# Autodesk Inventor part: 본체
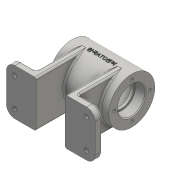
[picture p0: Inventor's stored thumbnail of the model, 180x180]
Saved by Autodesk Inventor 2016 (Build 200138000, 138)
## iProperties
Created: 2017-02
Part Number: 본체
Material: 일반
Document SubType Name: Modeling
Designer: CAMTIC
Density: 1 g/cm^3
Appearance: 기본값
Author: CAMTIC
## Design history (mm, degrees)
sketch "스케치1"
  geometry: L1 (52, 27)-(-52, 27); L2 (-52, 27)-(-52, -27); L3 (-52, -27)-(52, -27); L4 (52, -27)-(52, 27); L5 (52, 27)-(-52, -27); L6 (-52, 27)-(52, -27); 1 further point
  constraints: 12 end point, 2 midpoint, 2 parallel, 1 horizontal, 1 perpendicular
  dimensions: "d0" = 104 distance of L2.end L3.end; "d1" = 54 distance of L1.end L2.end
extrude "돌출1" new body sketch "스케치1" distance "d2" = 8; taper "d3" = 0 deg
sketch "스케치2"
  geometry: L1 (52, 0)-(52, 23.504) reference; L2 (35, -3.752)-(69, -3.752); L3 (69, -3.752)-(69, 27.256); L4 (69, 27.256)-(35, 27.256); L5 (35, 27.256)-(35, -3.752); L6 (35, -3.752)-(69, 27.256); L7 (69, -3.752)-(35, 27.256); 1 further point
  constraints: 14 end point, 3 midpoint, 2 parallel, 2 vertical, 1 horizontal, 1 perpendicular
  dimensions: "d5" = 17 distance between parallel lines of L1 L3
extrude "돌출2" cut sketch "스케치2" distance "d6" = 54; taper "d7" = 0 deg
node "작업 평면1"
sketch "스케치4"
  geometry: L1 (-35, 27)-(35, 27); L2 (35, 27)-(35, -27); L3 (35, -27)-(-35, -27); L4 (-35, -27)-(-35, 27); L5 (-35, 27)-(35, -27); L6 (35, 27)-(-35, -27); L7 (35, 0)-(-35, 0); 1 further point
  constraints: 14 end point, 4 midpoint, 2 parallel, 1 horizontal, 1 perpendicular
  dimensions: "d14" = 54 distance of L1.end L2.end; "d15" = 70 distance of L2.end L3.end
revolve "회전2" sketch "스케치4" stored, may be unused: angle "d16" = 90 deg
sketch "스케치5"
  geometry: L1 (-17, 27)-(-17, -27) reference; L2 (-17, -27)-(-25, -27); L3 (-25, -27)-(-25, 27); L4 (-25, 27)-(-17, 27); L5 (-17, 27)-(-17, -27); L6 (17, -27)-(17, 27) reference; L7 (17, -27)-(25, -27); L8 (25, -27)-(25, 27); L9 (25, 27)-(17, 27); L10 (17, 27)-(17, -27); 1 further point
  constraints: 16 end point, 4 parallel, 2 horizontal, 2 perpendicular
  dimensions: "d17" = 8 distance of L3.end L4.end; "d18" = 54 distance of L2.end L3.end; "d19" = 8 distance of L9.end L8.end; "d20" = 54 distance of L8.end L7.end
extrude "돌출3" join sketch "스케치5" stored distance "d21" = 0; taper "d22" = 0 deg
node "작업 평면2"
sketch "스케치6"
  geometry: L1 (0, 0)-(-5, 0); L2 (-5, 0)-(-5, 32); L3 (-5, 32)-(0, 32); L4 (0, 32)-(0, 0); L5 (27, -60)-(-27, -60) reference; C1 r 27 at (0, 0) reference; 1 further point
  constraints: 8 end point, 2 parallel, 1 coincident, 1 horizontal, 1 perpendicular
  dimensions: "d24" = 5 distance of L2.end L3.end; "d25" = 92 distance between parallel lines of L5 L3
revolve "회전3" sketch "스케치6" stored, may be unused: angle "d26" = 90 deg
node "작업 평면3"
sketch "스케치7"
  geometry: L1 (0, 0)-(-16.339, -25.16); L2 (0, 27)-(0, -27); A1 r 27 centre (0, 0) between (0, 27) and (0, -27) reference; 1 further point
  constraints: 4 end point, 2 point on circle
  dimensions: "d28" = 33 deg angle of L2 L1; "d29" = 30 distance of L1.start L1.end
node "작업 평면4"
sketch "스케치8"
  geometry: C1 r 6 at (0, 0); 1 further point
  constraints: 1 centre point
  dimensions: "d30" = 12 diameter of C1
extrude "돌출4" join sketch "스케치8" stored distance "d31" = 0; taper "d32" = 0 deg
sketch "스케치9"
  geometry: C1 r 16 at (0, 0); 1 further point
  constraints: 1 centre point
  dimensions: "d33" = 32 diameter of C1
extrude "돌출5" cut sketch "스케치9" distance "d34" = 12; taper "d35" = 0 deg
sketch "스케치10"
  geometry: C1 r 14 at (0, 0); 1 further point
  constraints: 1 centre point
  dimensions: "d36" = 28 diameter of C1
extrude "돌출6" cut sketch "스케치10" stored distance "d37" = 12; taper "d38" = 0 deg
sketch "스케치11"
  geometry: C1 r 14 at (0, 0) reference; C2 r 16 at (0, 0); 1 further point
  constraints: 1 centre point, 1 coincident
  dimensions: "d39" = 32 diameter of C2
extrude "돌출7" cut sketch "스케치11" distance "d40" = 12; taper "d41" = 0 deg
sketch "스케치12"
  geometry: C1 r 22 at (0, 0); 2 further points
  constraints: 1 centre point, 1 coincident
  dimensions: "d42" = 44 diameter of C1
extrude "돌출8" cut sketch "스케치12" distance "d43" = 20; taper "d45" = 0 deg; dims "d44" = 20, "d46" = 0
sketch "스케치13"
  geometry: C1 r 16 at (0, 0) reference; 2 further points
  dimensions: "d47" = 21 distance of point (0, 21) C1.centre
hole "구멍1" sketch "스케치13" at (0, 21) diameter "d48" = 3.242; stored, may be unused: countersink angle "d52" = 90 deg, drill point angle "d54" = 118 deg; dims "d49" = 8, "d50" = 4, "d51" = 2, "d53" = 10
sketch "스케치14"
  geometry: 2 further points
hole "구멍2" sketch "스케치14" at (0, 21) diameter "d58" = 3.242; stored, may be unused: countersink angle "d62" = 90 deg, drill point angle "d64" = 118 deg; dims "d59" = 8, "d60" = 4, "d61" = 2, "d63" = 10
sketch "스케치15"
  geometry: C1 r 5 at (0, 0) reference; 2 further points
  constraints: 1 coincident
hole "구멍3" sketch "스케치15" at (0, 0) diameter "d68" = 5.188; stored, may be unused: countersink angle "d72" = 90 deg, drill point angle "d74" = 118 deg; dims "d69" = 20, "d70" = 4, "d71" = 2, "d73" = 20
sketch "스케치16"
  geometry: C1 r 6 at (0, 0) reference; 2 further points
  constraints: 1 coincident
hole "구멍4" sketch "스케치16" at (0, 0) diameter "d75" = 5.188; stored, may be unused: countersink angle "d79" = 90 deg, drill point angle "d81" = 118 deg; dims "d76" = 20, "d77" = 4, "d78" = 2, "d80" = 20
sketch "스케치17" dims "d82" = 9
  geometry: L1 (-25, 27)-(-52, 27) reference; L2 (-52, 27)-(-52, -27) reference; L3 (-39.402, 21.5)-(-36.804, 17); L4 (-36.804, 17)-(-39.402, 12.5); L5 (-39.402, 12.5)-(-44.598, 12.5); L6 (-44.598, 12.5)-(-47.196, 17); L7 (-47.196, 17)-(-44.598, 21.5); L8 (-44.598, 21.5)-(-39.402, 21.5); 4 further points
  constraints: 12 end point, 1 coincident, 1 midpoint, 1 vertical alignment, 15 other
  dimensions: "d83" = 10 distance from line of L1 point (-42, 17); "d84" = 10 distance from line of L2 point (-42, 17)
extrude "돌출9" cut sketch "스케치17" distance "d85" = 3; taper "d86" = 0 deg
fillet "모깎기1" dims "d93" = 10
sketch "스케치19"
  geometry: C1 r 2.5 at (-42, 17); A1 r 10 centre (-42, 17) between (-42, 27) and (-52, 17) reference; 1 further point
  constraints: 1 centre point, 1 coincident
  dimensions: "d94" = 5 diameter of C1
extrude "돌출10" cut sketch "스케치19" stored distance "d95" = 3; taper "d96" = 0 deg
node "작업 평면5"
sketch "스케치20"
  geometry: L1 (-35, 87)-(35, 87) reference; L2 (-35, 33)-(-35, 87) reference; 2 further points
  constraints: 1 other
  dimensions: "d104" = 27 distance from line of L1 point (0, 60); "d105" = 35 distance from line of L2 point (0, 60)
feature "엠보싱1" sketch "스케치20" dims "d106" = 0.5, "d107" = 0
fillet "모깎기2" dims "d108" = 3
chamfer "모따기1" distance "d109" = 1; stored, may be unused: second distance "d110" = 2, angle "d111" = 45 deg
fillet "모깎기3" dims "d112" = 0.3
fillet "모깎기4" dims "d113" = 2
fillet "모깎기5" dims "d114" = 2
node "솔리드1"
pattern_circular "원형 패턴1" dims angle "d56" = 360 deg
pattern_circular "원형 패턴2" dims angle "d66" = 360 deg
pattern_linear "직사각형 패턴1" dims "d89" = 84, "d92" = 34
pattern_linear "직사각형 패턴2" dims "d99" = 84, "d102" = 34
other parameters: "d23" = -25, "d27" = -35
